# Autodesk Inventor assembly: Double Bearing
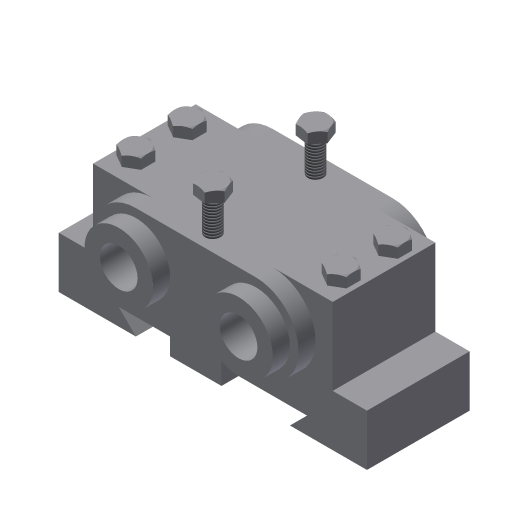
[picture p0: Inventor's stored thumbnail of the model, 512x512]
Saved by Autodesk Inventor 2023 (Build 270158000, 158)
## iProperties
Created: 2002-02
Part Number: Double Bearing
Document SubType Name: Assembly
Designer: ***
Control State: 0
Master: False
Checked Out: False
Shininess: 64.0
Length Units: 11269
Angle Units: 11279
Time Units: 11290
Mass Units: 11283
Length Display Precision: 3
Angle Display Precision: 2
Density: 0.0
Volumn: 0.0
Area: 0.0
PropertySet Name: Model Information
Author: ***
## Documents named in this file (5)
- D:\PROJECTS\Project 2022\Autodesk Inventor For Professional 2023\RESOURCES INVENTOR 2023\RESOURCES INVENTOR 2023\Inventor_2023_tut\Inventor_2023_tut\c10_Inv_2023_tut\c10_Inv_tut_2023\c10_tut03_inv\Double Bearing Assembly\Double Bearing.iam
- D:\PROJECTS\Project 2022\Autodesk Inventor For Professional 2023\RESOURCES INVENTOR 2023\RESOURCES INVENTOR 2023\Inventor_2023_tut\Inventor_2023_tut\c10_Inv_2023_tut\c10_Inv_tut_2023\c10_tut03_inv\Double Bearing Assembly\Base.ipt
- D:\PROJECTS\Project 2022\Autodesk Inventor For Professional 2023\RESOURCES INVENTOR 2023\RESOURCES INVENTOR 2023\Inventor_2023_tut\Inventor_2023_tut\c10_Inv_2023_tut\c10_Inv_tut_2023\c10_tut03_inv\Double Bearing Assembly\Cap.ipt
- D:\PROJECTS\Project 2022\Autodesk Inventor For Professional 2023\RESOURCES INVENTOR 2023\RESOURCES INVENTOR 2023\Inventor_2023_tut\Inventor_2023_tut\c10_Inv_2023_tut\c10_Inv_tut_2023\c10_tut03_inv\Double Bearing Assembly\Bushing.ipt
- D:\PROJECTS\Project 2022\Autodesk Inventor For Professional 2023\RESOURCES INVENTOR 2023\RESOURCES INVENTOR 2023\Inventor_2023_tut\Inventor_2023_tut\c10_Inv_2023_tut\c10_Inv_tut_2023\c10_tut03_inv\Double Bearing Assembly\Bolt.ipt
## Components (10 placed, 4 different names)
1. Base:1 — Insert:1, Insert:2
2. Cap:1 — Insert:1, Insert:2, Insert:3, Insert:4, Insert:5, Insert:6
3. Bushing:1 — Insert:3
4. Bushing:2 — Insert:4
5. Bolt:1 — Insert:5
6. Bolt:6
7. Bolt:7
8. Bolt:8
9. Bolt:5 — Insert:6
10. Bolt:9
## Component patterns: Component Pattern 1 (4 elements), Component Pattern 2 (2 elements)
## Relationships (6: Insert 6)
- Insert:1: Base:1 ↔ Cap:1
- Insert:2: Base:1 ↔ Cap:1
- Insert:3: Cap:1 ↔ Bushing:1
- Insert:4: Cap:1 ↔ Bushing:2
- Insert:5: Cap:1 ↔ Bolt:1
- Insert:6: Cap:1 ↔ Bolt:5
